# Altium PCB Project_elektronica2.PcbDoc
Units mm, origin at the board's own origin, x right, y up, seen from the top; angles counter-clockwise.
Board outline 152.4 x 101.6 mm, 2 copper layers (Top Layer, Bottom Layer); 37 components, 26 nets, 117 pads, 8 vias.
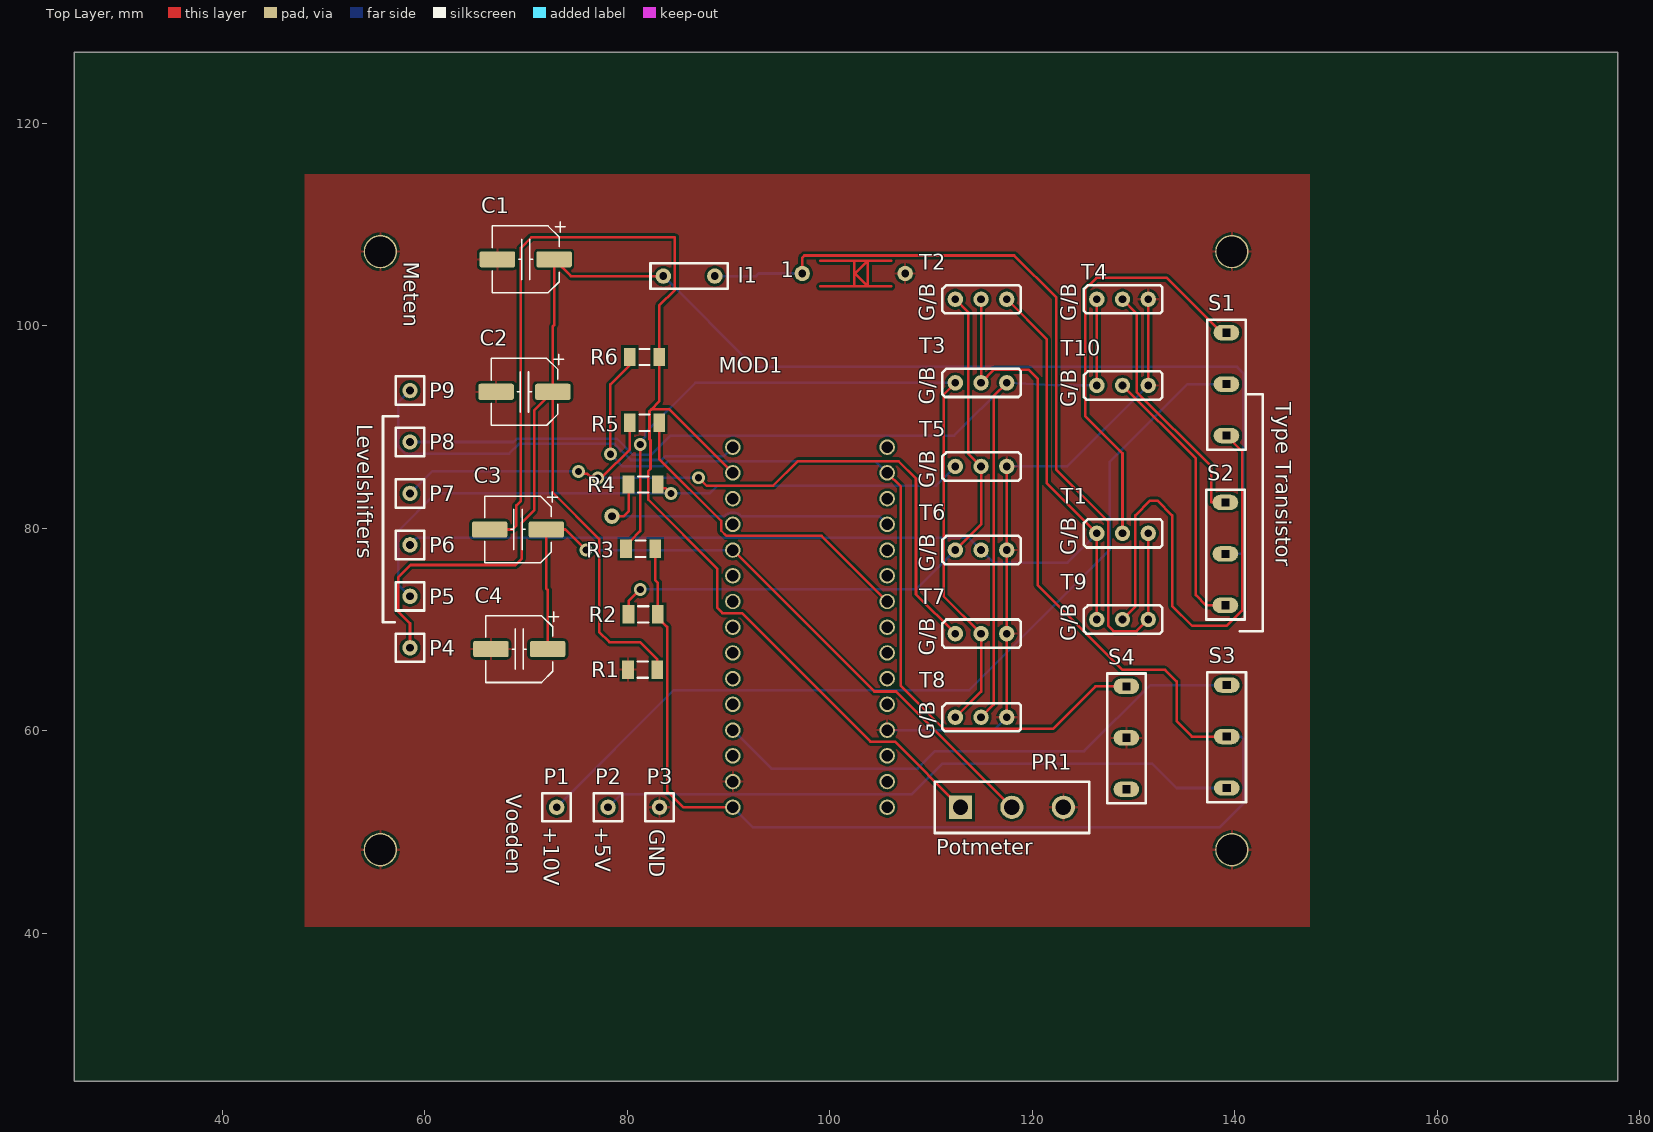
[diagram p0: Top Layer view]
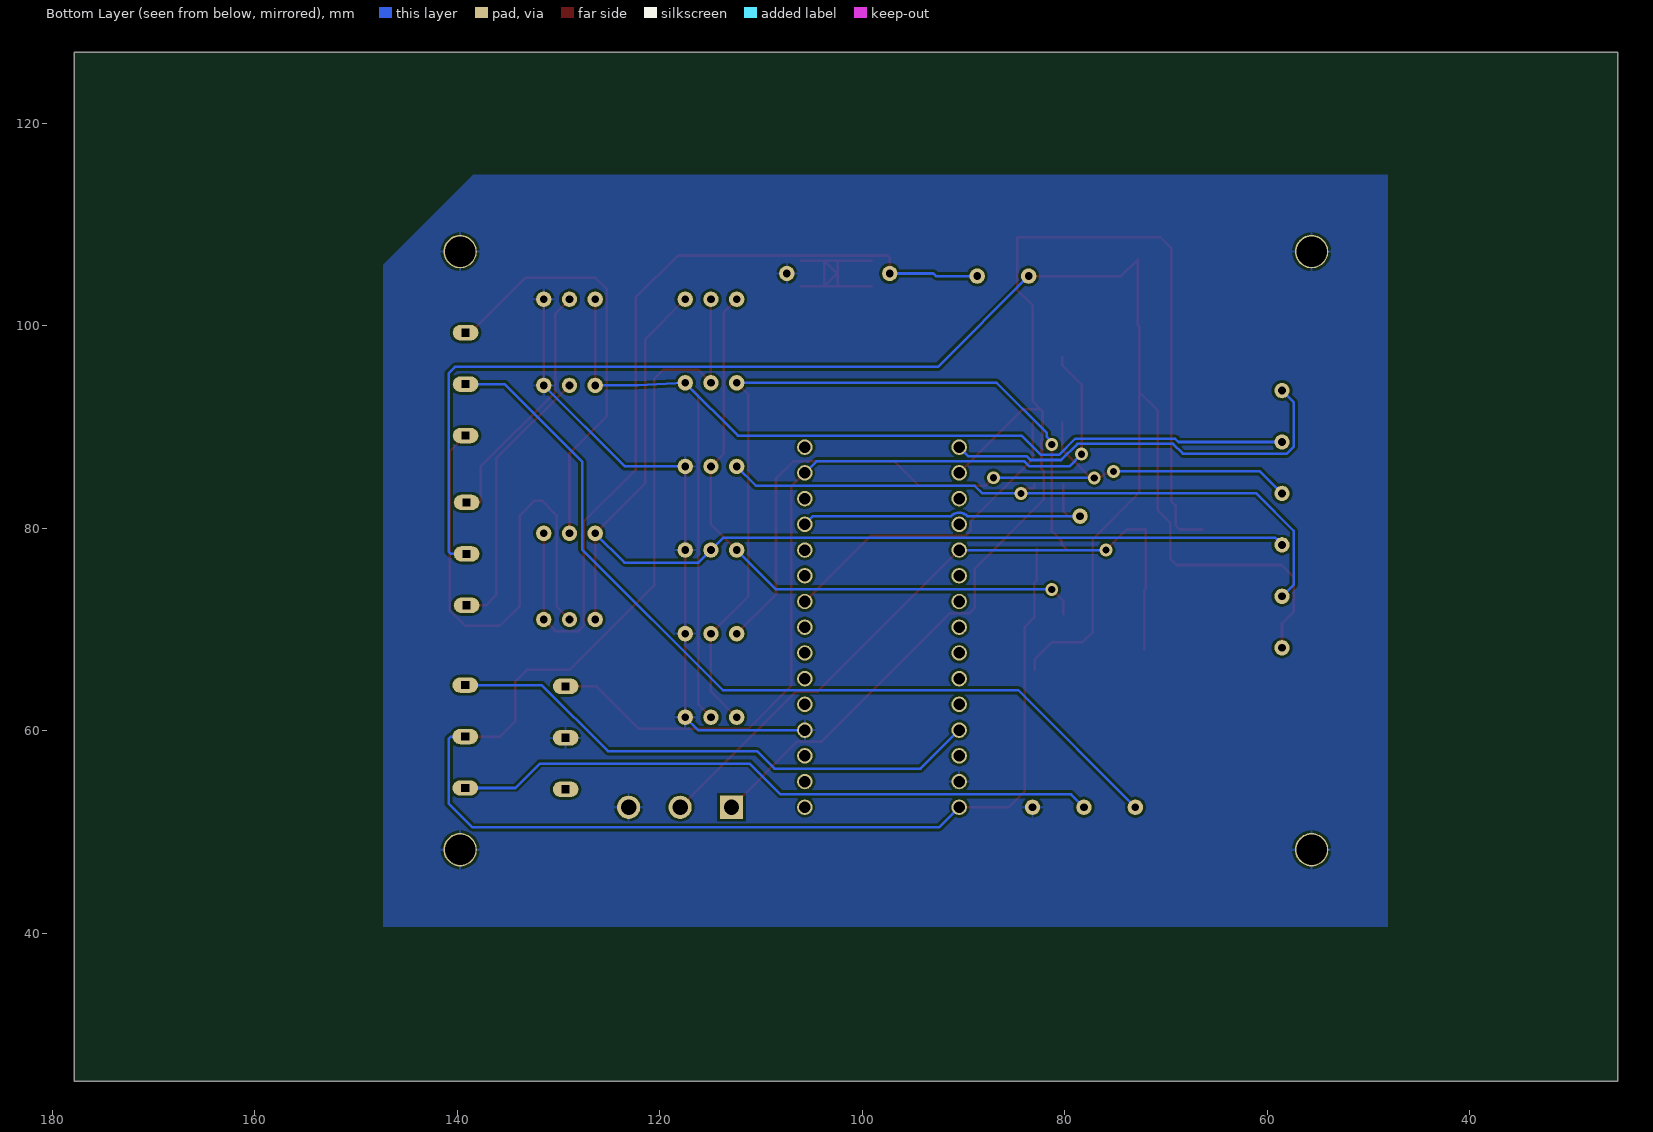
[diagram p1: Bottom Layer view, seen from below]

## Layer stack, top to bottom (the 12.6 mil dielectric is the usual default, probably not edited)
Top Solder: solder mask 0.0102, Solder Resist, Dk 3.5
Top Layer: signal copper 0.0356
Dielectric 1: dielectric 0.32, FR-4, Dk 4.8
Bottom Layer: signal copper 0.0356
Bottom Solder: solder mask 0.0102, Solder Resist, Dk 3.5

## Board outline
25.4,25.4 177.8,25.4 177.8,127 25.4,127

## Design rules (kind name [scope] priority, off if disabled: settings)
Clearance [All] p1: gap=0.254 ignorepadtopadclearanceinfootprint=FALSE
DiffPairsRouting [All] p1: maxlimit=1.27 minlimit=0.635 mostfreqgap=0.889 toplayer_minwidth=0.381 toplayer_maxwidth=0.508 toplayer_prefwidth=0.508 bottomlayer_minwidth=0.381 bottomlayer_maxwidth=0.508 bottomlayer_prefwidth=0.508 maxuncoupledlength=12.7
PolygonConnect [All] p1: connectstyle=Relief reliefconductorwidth=0.254 reliefentries=4 polygonreliefangle="90 Angle" airgapwidth=0.254
RoutingVias [All] p1: holewidth=0.711 width=1.27 viastyle="Through Hole" minholewidth=0.711 minwidth=1.27 maxholewidth=0.711 maxwidth=1.27
SolderMaskExpansion [All] p1: expansion=0.102 istentingtop=FALSE
SupplyNets "Schematic Supply Nets_5" [InNet('GND')] p1: voltage=0.000
SupplyNets "Schematic Supply Nets_4" [InNet('+3V3')] p2: voltage=0.000
SupplyNets "Schematic Supply Nets_2" [InNet('+10V')] p3: voltage=0.000
SupplyNets "Schematic Supply Nets_1" [InNet('+5V')] p4: voltage=0.000
SupplyNets "Schematic Supply Nets" [InNet('+5V-EXT')] p5: voltage=0.000
Width [All] p1: maxlimit=0.254 minlimit=0.254 preferedwidth=0.254
29 further rules are at their usual default settings.

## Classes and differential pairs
component class Project_elektronica2: PR1 S3 S4 T9 T10

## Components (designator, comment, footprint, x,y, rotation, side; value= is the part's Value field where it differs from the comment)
1 "1N4148" "1n4148 [DIODE]" 107.442,106.426 r180 top
C1 "100nF" CAP_ELEC_6.3x4.2 69.977,106.553 r0 top
C2 "100nF" CAP_ELEC_6.3x4.2 69.85,93.472 r0 top
C3 "1uF" CAP_ELEC_6.3x4.2 69.215,79.883 r0 top
C4 "1uF" CAP_ELEC_6.3x4.2 69.342,68.072 r0 top
I1 "851-RCH8011NP-101L" "Spoel 100uH" 88.646,104.902 r180 top
MOD1 "F303K8" F303K8 105.664,49.911 r180 top
P1 "PIN" PIN 73.025,52.451 r0 top
P2 "PIN" PIN 78.105,52.451 r0 top
P3 "PIN" PIN 83.185,52.451 r0 top
P4 "PIN" PIN 58.547,68.199 r0 top
P5 "PIN" Pin 58.547,73.279 r0 top
P6 "PIN" PIN 58.547,78.359 r0 top
P7 "PIN" PIN 58.547,83.439 r0 top
P8 "PIN" PIN 58.547,88.519 r0 top
P9 "PIN" PIN 58.547,93.599 r0 top
PR1 "Potmeter" "PM component" 112.903,52.451 r0 top
R1 "1K" R1206 81.526,66.04 r0 top
R2 "1K" R1206 81.579,71.501 r0 top
R3 "1K" R1206 81.325,77.978 r0 top
R4 "330" R1206 81.579,84.328 r0 top
R5 "330" R1206 81.706,90.424 r0 top
R6 "10K" R1206 81.706,96.901 r0 top
S1 "" "schakelaar 3-pin" 139.167,99.314 r0 top
S2 "" "schakelaar 3-pin" 139.065,82.55 r0 top
S3 "" "schakelaar 3-pin" 139.192,64.516 r0 top
S4 "" "schakelaar 3-pin" 129.286,64.389 r0 top
T1 "IRF540" (MOS)FET 131.445,79.502 r90 top
T2 "BD681" (MOS)FET 117.475,102.616 r90 top
T3 "BD681" (MOS)FET 117.475,94.361 r90 top
T4 "IRF540" (MOS)FET 131.445,102.616 r90 top
T5 "BD681" (MOS)FET 117.475,86.106 r90 top
T6 "BD680" (MOS)FET 117.475,77.851 r90 top
T7 "BD681" (MOS)FET 117.475,69.596 r90 top
T8 "BD680" (MOS)FET 117.475,61.341 r90 top
T9 "IRF540" (MOS)FET 131.445,70.993 r90 top
T10 "IRF540" (MOS)FET 131.445,94.107 r90 top

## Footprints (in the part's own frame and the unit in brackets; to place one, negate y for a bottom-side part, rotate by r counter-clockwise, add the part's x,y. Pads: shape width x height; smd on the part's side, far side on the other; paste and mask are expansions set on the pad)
"1n4148 [DIODE]" [mil]
  round 60 hole 30: +(0,50) -(400,50)
  Top Layer lines w10: 330,100 55,100 ; 330,0 55,0 ; 197.5,100 197.5,0 ; 195,50 145,0 145,100 195,50
(MOS)FET [mil]
  round 60 hole 30: 1(0,200) 2(0,100) 3(0,0)
  silkscreen extent -55,-55 55,250
CAP_ELEC_6.3x4.2 [mm] "Capacitor, polarized, aluminum can; 6.3x4.2mm DxH"
  round 0.508 on Mech15: 0(0,0)
  rrect25% 3.5x1.6 smd: 1(2.8,0) 2(-2.8,0)
  silkscreen extent -3.3,-3.3 3.9,3.7, body extent -3.3,-3.3 3.3,3.3, height 4.23
F303K8 [mil] "component"
  round 60 hole 45: 1(0,-100) 2(0,-200) 3(0,-300) 4(0,-400) 5(0,-500) 6(0,-600) 7(0,-700) 8(0,-800) 9(0,-900) 10(0,-1000) 11(0,-1100) 12(0,-1200) 13(0,-1300) 14(0,-1400) 15(0,-1500) 16(600,-1500) 17(600,-1400) 18(600,-1300) 19(600,-1200) 20(600,-1100) 21(600,-1000) 22(600,-900) 23(600,-800) 24(600,-700) 25(600,-600) 26(600,-500) 27(600,-400) 28(600,-300) 29(600,-200) 30(600,-100)
  body extent -65,-1759 665,289, height 111
PIN [mil]
  round 60 hole 30: 10(0,0)
  silkscreen extent -55,-55 55,55
Pin [mil]
  round 60 hole 30: 10(0,0)
  silkscreen extent -55,-55 55,55
"PM component" [mil] "Potmeter"
  rect 90x90 hole 60: 1(0,0)
  round 90 hole 60: 2(200,0) 3(400,0)
  silkscreen extent -100,-100 500,100
R1206 [mm] "Chip Resistor, Body 3.2x1.6mm, IPC Medium Density"
  rect 1.15x1.8 smd: 1(-1.45,0) 2(1.45,0)
  silkscreen extent -0.5,-0.8 0.5,0.8, body extent -1.67,-0.87 1.67,0.87, height 0.75
"schakelaar 3-pin" [mil]
  oval 100x60 hole 30 square: 1(0,0) 2(0,-200) 3(0,-400)
  silkscreen extent -75,-455 75,50
"Spoel 100uH" [mil]
  round 60 hole 30: 1(0,0) 2(200,0)
  silkscreen extent -50,-50 250,50

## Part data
1: "Diode"
C1 C2 C3 C4: library part Elco_SMD_6.3mm, "Elco SMD 6.3mm"
I1: "Spoel 100uH"
MOD1: "Programmable IC"
R1 R2 R3 R4 R5 R6: library part Resistor_1206, "SMD Resistor 1206"
S1 S2 S3 S4: library part "Tuimelschakelaar 3-pin"
T1 T4 T9 T10: "NPN MOSFET"
T2 T3 T5 T7: "NPN BJT TH"
T6 T8: "PNP BJT TH"

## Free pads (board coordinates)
  round 1.524 hole 0.762: 161(78.49,81.198)
  oval 3.305x3.302 hole 3: "Mount 1"(55.626,107.315)
  round 3.302 hole 3: "Mount 2"(139.7,107.315) "Mount 3"(55.626,48.26) "Mount 4"(139.7,48.26)

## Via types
v1: diameter 1.27, hole 0.711, Top Layer to Bottom Layer, 8 vias

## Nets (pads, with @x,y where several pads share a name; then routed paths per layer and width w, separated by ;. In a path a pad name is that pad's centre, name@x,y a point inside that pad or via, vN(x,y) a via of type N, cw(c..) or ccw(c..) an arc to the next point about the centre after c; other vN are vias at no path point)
+3V3: C3.2 MOD1.17 PR1.1 R6.2 | length 129.4
  Top Layer w0.254: C3.2 68.662,79.883 69.043,80.264 69.043,82.265 69.494,82.716 69.494,107.696 70.536,108.737 84.684,108.737 84.709,108.712 84.709,103.53 83.156,101.977 R6.2 83.156,92.529 82.372,91.745 ; MOD1.17 84.15,91.745 82.372,91.745 ; PR1.1 106.426,58.928 104.013,58.928 91.313,71.628 89.408,71.628 88.9,72.136 88.9,75.997 82.073,82.824 82.073,85.643 82.296,85.866 82.296,88.686 82.2,88.782 82.2,91.573 82.372,91.745
+5V: MOD1.30 R2.2 R3.2 S3.2 T2.2 T3.2 | length 154.1
  Top Layer w0.254: R3.2 82.775,74.854 83.029,74.6 R2.2 83.029,71.171 83.947,70.253 83.947,54.077 85.573,52.451 MOD1.30 ; T2.2 T3.2 116.23,95.656 119.634,95.656 120.548,94.742 120.548,74.371 128.905,66.015 133.096,66.015 134.239,64.872 134.239,60.96 135.763,59.436 S3.2
  Bottom Layer w0.254: MOD1.30 92.405,50.47 138.481,50.47 140.843,52.832 140.843,59.182 140.589,59.436 S3.2
+5V-EXT: P2.10 S3.3 | length 63.9
  Bottom Layer w0.254: P2.10 79.375,53.721 108.077,53.721 111.125,56.769 131.826,56.769 134.239,54.356 S3.3
+10V: P1.10 S1.2 | length 88.5
  Bottom Layer w0.254: P1.10 84.582,64.008 113.767,64.008 127.635,77.876 127.635,86.563 135.306,94.234 S1.2
GND: 1.+ "pad.Mount 1" "pad.Mount 2" "pad.Mount 3" "pad.Mount 4" C1.2 C2.2 C4.2 MOD1.4 MOD1.29 P3.10 PR1.3 R1.1 S4.2 T4.3 T5.3 T6.3 T7.3 T8.3 T10.3 | length 62.9
  Top Layer w0.254: T8.3 T7.3 T6.3 T5.3 ; T10.3 T4.3
  Bottom Layer w0.254: MOD1.4 116.205,60.071 T8.3 ; T5.3 123.444,86.106 T10.3
Net1_-: 1.- I1.1 T1.3 T9.3 | length 84.9
  Top Layer w0.254: 1.- 97.282,106.731 97.485,106.934 118.212,106.934 122.377,102.768 122.377,85.776 127.508,80.645 127.508,70.358 128.016,69.85 130.302,69.85 T9.3 T1.3
  Bottom Layer w0.254: I1.1 92.71,104.902 92.964,105.156 1.-
NetC1_1: C1.1 C2.1 I1.2 P4.10 R1.2 S2.2 | length 177
  Top Layer w0.254: P4.10 58.547,70.612 57.404,71.755 57.404,75.184 58.598,76.378 68.961,76.378 69.571,76.987 69.571,80.518 70.815,81.763 70.815,91.643 C2.1@72.644,93.472 ; R1.2 82.976,67.062 81.28,68.758 78.232,68.758 77.216,69.774 77.216,78.943 72.644,83.515 C2.1@72.644,93.472 ; I1.2 74.428,104.902 C1.1 72.777,100.076 72.65,99.949 C2.1 C2.1@72.644,93.472
  Bottom Layer w0.254: I1.2 92.532,95.936 140.208,95.936 140.843,95.301 140.843,77.724 140.589,77.47 S2.2
NetC3_1: C3.1 C4.1 MOD1.20 PR1.2 | length 69.2
  Top Layer w0.254: C4.1 72.142,73.914 72.003,74.053 72.003,79.883 C3.1 73.889,79.883 v1(75.921,77.851) ; MOD1.20 104.394,63.881 106.553,63.881 PR1.2
  Bottom Layer w0.254: v1(75.921,77.851) MOD1.20
NetMOD1_9: MOD1.9 R5.2 | length 32.5
  Top Layer w0.254: R5.2 83.156,86.857 89.281,80.732 89.281,79.756 89.789,79.248 99.187,79.248 MOD1.9
NetMOD1_12: MOD1.12 pad.161 R4.1 | length 32.2
  Top Layer w0.254: pad.161 79.658,81.198 80.129,81.669 R4.1
  Bottom Layer w0.254: pad.161 89.615,81.198 cw(c90.424,80.391) 91.233,81.198 104.857,81.198 MOD1.12
NetMOD1_14: MOD1.14 R6.1 S4.1 | length 86.2
  Top Layer w0.254: v1(78.338,87.317) 78.338,94.213 80.256,96.131 R6.1 ; MOD1.14 107.01,84.125 107.01,64.44 111.252,60.198 122.047,60.198 126.238,64.389 S4.1
  Bottom Layer w0.254: v1(78.338,87.317) 79.538,86.117 83.493,86.117 83.99,86.614 104.521,86.614 MOD1.14
NetMOD1_16: MOD1.16 P9.10 | length 40.9
  Bottom Layer w0.254: P9.10 57.404,92.456 57.404,88.046 58.074,87.376 68.344,87.376 69.301,88.333 78.759,88.333 80.351,86.741 83.398,86.741 83.779,87.122 89.535,87.122 MOD1.16
NetMOD1_27: MOD1.27 S3.1 | length 53.8
  Bottom Layer w0.254: MOD1.27 94.234,56.261 108.661,56.261 110.388,57.988 125.12,57.988 131.648,64.516 S3.1
NetP5_10: P5.10 R4.2 T5.1 | length 66.4
  Top Layer w0.254: R4.2 83.029,83.972 83.795,83.972 v1(84.328,83.439)
  Bottom Layer w0.254: P5.10 57.404,74.422 57.404,79.756 61.087,83.439 v1(84.328,83.439) 88.138,83.439 88.9,84.201 110.49,84.201 T5.1
NetP6_10: 
NetP7_10: P7.10 R5.1 T7.1 | length 77.1
  Top Layer w0.254: v1(75.184,85.598) 75.378,85.404 76.034,85.404 76.281,85.157 76.895,85.157 v1(77.089,84.963) 77.283,85.157 77.615,85.157 80.256,87.799 R5.1 ; v1(87.046,84.988) 87.833,84.201 94.412,84.201 96.825,86.614 106.807,86.614 108.509,84.912 108.509,73.482 T7.1
  Bottom Layer w0.254: P7.10 60.757,85.649 75.133,85.649 v1(75.184,85.598) ; v1(77.089,84.963) 77.102,84.976 87.033,84.976 v1(87.046,84.988)
NetP8_10: 
NetP_10: 
NetR2_1: R2.1 T2.1 T5.2 T6.1 | length 62.5
  Top Layer w0.254: R2.1 80.129,72.814 v1(81.28,73.965) ; T6.1 114.935,80.391 T5.2 113.665,87.376 113.665,101.346 T2.1
  Bottom Layer w0.254: v1(81.28,73.965) 108.509,73.965 T6.1
NetR3_1: R3.1 T3.1 T7.2 T8.1 | length 81
  Top Layer w0.254: R3.1 80.323,78.426 80.323,78.756 81.28,79.713 v1(81.28,88.265) ; T8.1 114.935,63.881 T7.2 111.252,73.279 111.252,93.218 T3.1
  Bottom Layer w0.254: v1(81.28,88.265) 81.28,88.54 81.758,89.018 81.758,89.403 86.716,94.361 T3.1
NetS1_1: S1.1 T1.2 | length 42.3
  Top Layer w0.254: T1.2 128.905,87.401 125.222,91.084 125.222,103.632 126.314,104.724 133.274,104.724 138.684,99.314 S1.1
NetS1_3: S1.3 T9.2 | length 50.9
  Top Layer w0.254: T9.2 130.175,72.263 130.175,81.28 131.623,82.728 132.359,82.728 133.807,81.28 133.807,72.339 135.788,70.358 139.192,70.358 140.716,71.882 140.716,87.605 S1.3
NetS2_1: S2.1 T4.2 | length 25.1
  Top Layer w0.254: T4.2 130.302,101.219 130.302,93.472 137.668,86.106 137.668,82.55 S2.1
NetS2_3: S2.3 T10.2 | length 27
  Top Layer w0.254: T10.2 136.144,86.868 136.144,73.406 137.16,72.39 S2.3
Vg1: P6.10 T1.1 T2.3 T6.2 T9.1 | length 105.6
  Top Layer w0.254: T2.3 121.412,98.679 121.412,84.455 T1.1 T9.1
  Bottom Layer w0.254: P6.10 59.258,79.07 113.716,79.07 T6.2 116.18,76.606 123.469,76.606 T1.1
Vg2: P8.10 T3.3 T4.1 T8.2 T10.1 | length 114.1
  Top Layer w0.254: T8.2 116.18,62.586 116.18,93.066 T3.3 ; T10.1 T4.1
  Bottom Layer w0.254: P8.10 68.769,88.519 69.091,88.841 78.969,88.841 80.561,87.249 82.366,87.249 84.271,89.154 112.268,89.154 T3.3 122.174,94.107 T10.1
pads on no net: C1.0 C2.0 C3.0 C4.0 MOD1.1 MOD1.2 MOD1.3 MOD1.5 MOD1.6 MOD1.7 MOD1.8 MOD1.10 MOD1.11 MOD1.13 MOD1.15 MOD1.18 MOD1.19 MOD1.21 MOD1.22 MOD1.23 MOD1.24 MOD1.25 MOD1.26 MOD1.28 S4.3

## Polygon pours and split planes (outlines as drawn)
GND on Top Layer "GND_L01_P000" (solid, pour order 0): 48.133,114.935 147.383,114.935 147.383,40.64 48.133,40.64
GND on Bottom Layer "GND_L02_P001" (solid, pour order 1): 48.107,114.927 138.404,114.927 147.294,106.037 147.294,40.632 48.107,40.632

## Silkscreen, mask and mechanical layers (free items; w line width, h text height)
Top Overlay:
  lines w0.254: 57.023,70.739 55.88,70.739 55.88,91.059 57.404,91.059 ; 140.462,69.85 142.748,69.85 142.748,93.218 141.224,93.218
  text "Meten" at 57.912,106.299 h1.52 r270
  text "Type Transistor" at 144.018,92.456 h1.52 r270
  text "Levelshifters" at 53.34,90.297 h1.52 r270
  text "Voeden" at 68.072,53.721 h1.52 r270
  text "+10V" at 71.755,50.546 h1.52 r270
  text "+5V" at 76.835,50.546 h1.52 r270
  text "GND" at 82.169,50.292 h1.52 r270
